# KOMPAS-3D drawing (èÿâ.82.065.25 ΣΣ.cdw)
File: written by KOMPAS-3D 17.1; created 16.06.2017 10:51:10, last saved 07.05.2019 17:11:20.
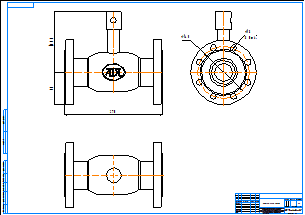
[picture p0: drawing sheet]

Sheet 1: A1, landscape

Title block, sheet 1: name: КШГ.82.065.25 фф; material: Внимание! Данный продукт является объектом авторского права ООО «Торговый Дом АДЛ». / Запрещается изменение, копирование, распространение / (в том числе путем копирования на другие сайты и ресурсы в Интернете) / или любое иное использование информации и объектов без предварительного / согласия правообладателя (ООО «Торговый Дом АДЛ»).; scale: 1:1; sheets: 1; organisation: ООО "Торговый дом АДЛ"; sheet format: A1; stored path: C:\Users\tra\Desktop\2д чертежи\Шаровые краны БИВАЛ\КШ_Бивал_серия_82_85\KOMPAS 2D\КШГ.82.065.25 фф.cdw

Views: Спереди 1, Проекционный вид 2, Проекционный вид 3
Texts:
  Klimkovich
  ADL
Dimensions and other numbers on the sheet: 270; 167,3; 90; 145; 18; 8 Отв.; 1:1; 1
